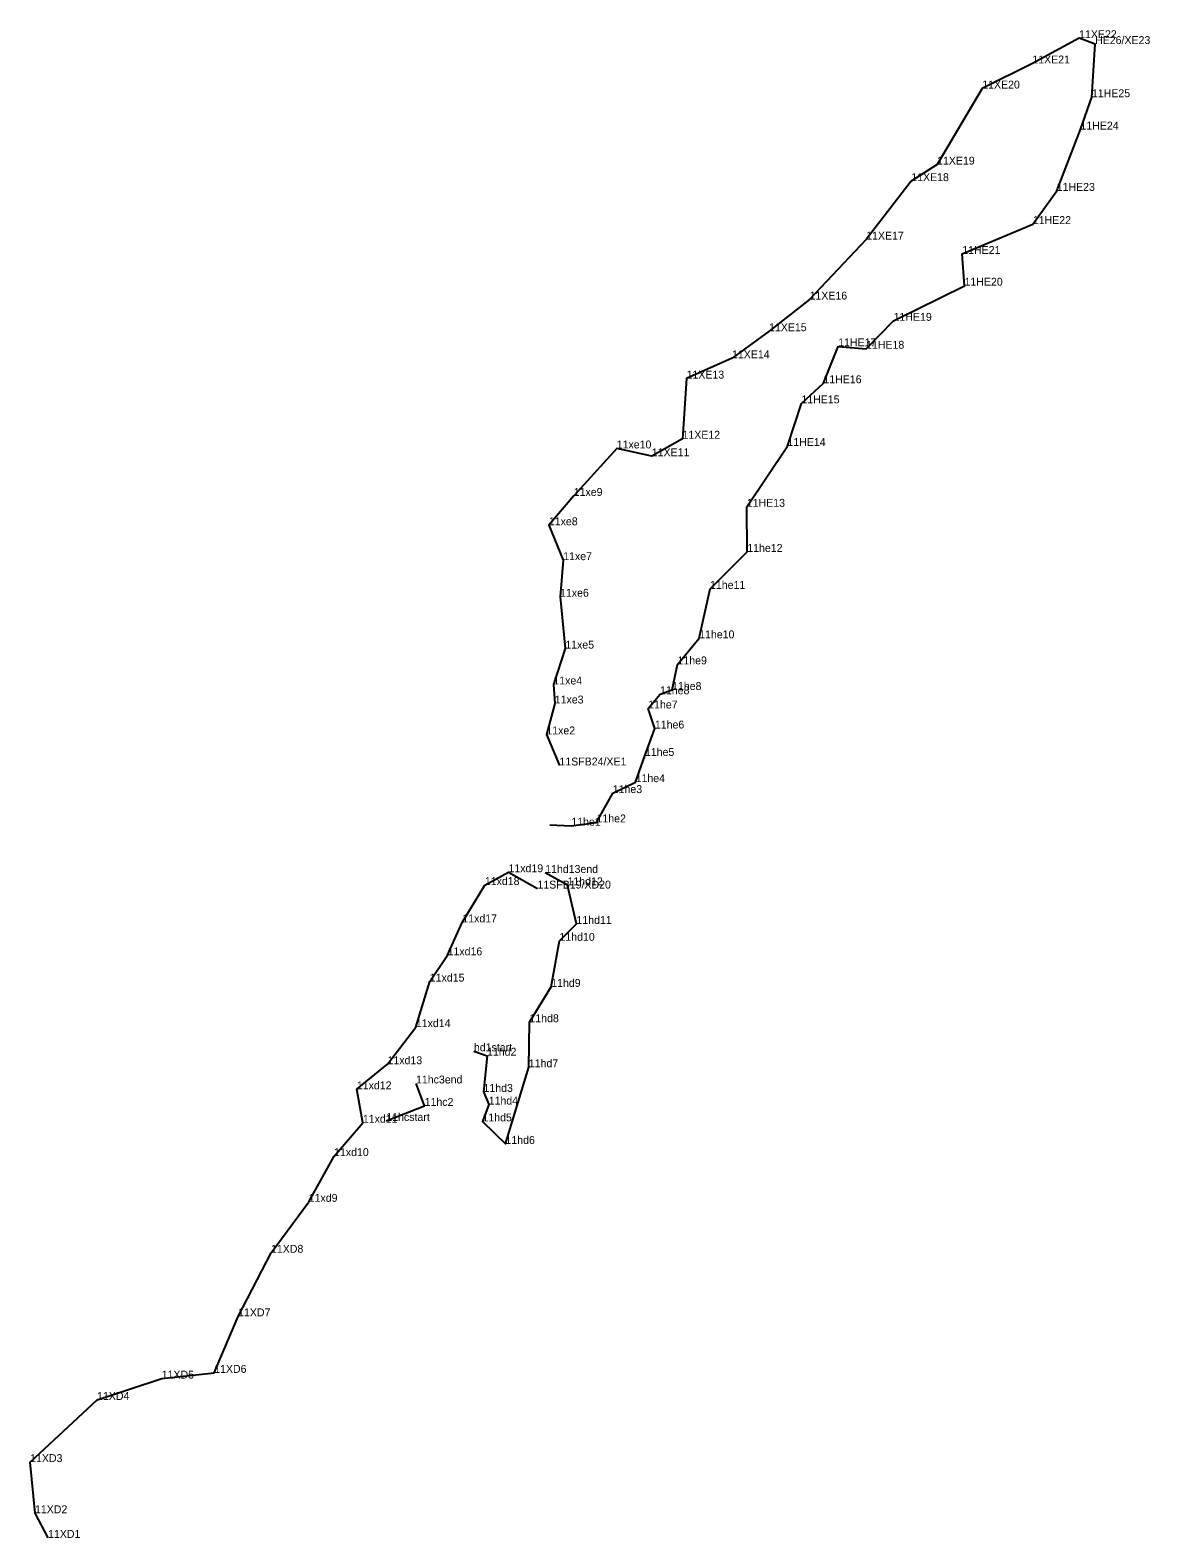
# Model space of a CAD drawing. Extents: x 2072529 to 2267990, y 436423 to 470008.
# Drawn here: x 2235708 to 2236417, y 448547 to 449501 of the extents above; entities that cross this region are included whole.
import ezdxf

# ---------------------------------------------------------------- set-up
doc = ezdxf.new("R2010")
doc.units = 0
doc.layers.add('Level 3', color=7, linetype='Continuous')
doc.layers.add('Old_Level_52', color=7, linetype='Continuous')

msp = doc.modelspace()

# ---------------------------------------------------------------- linework, layer by layer
at = {"layer": 'Level 3'}
for p, q in [((2236372.381, 449496.4), (2236372.381, 449496.4)), ((2236382.487, 449492.667), (2236382.487, 449492.667)), ((2236342.766, 449480.407), (2236342.766, 449480.407)), ((2236311.041, 449464.52), (2236311.041, 449464.52)), ((2236380.495, 449459.029), (2236380.495, 449459.029)), ((2236373.231, 449438.548), (2236373.231, 449438.548)), ((2236282.461, 449416.334), (2236282.461, 449416.334)), ((2236266.127, 449405.869), (2236266.127, 449405.869)), ((2236358.182, 449399.707), (2236358.182, 449399.707)), ((2236343.073, 449378.68), (2236343.073, 449378.68)), ((2236237.577, 449368.843), (2236237.577, 449368.843)), ((2236298.377, 449359.711), (2236298.377, 449359.711)), ((2236299.825, 449339.635), (2236299.825, 449339.635)), ((2236201.726, 449330.85), (2236201.726, 449330.85)), ((2236176.077, 449310.812), (2236176.077, 449310.812)), ((2236254.906, 449317.386), (2236254.906, 449317.386)), ((2236219.847, 449301.214), (2236219.847, 449301.214)), ((2236152.626, 449293.629), (2236152.626, 449293.629)), ((2236237.488, 449299.692), (2236237.488, 449299.692)), ((2236123.874, 449280.795), (2236123.874, 449280.795)), ((2236210.458, 449277.837), (2236210.458, 449277.837)), ((2236196.532, 449265.111), (2236196.532, 449265.111)), ((2236079.636, 449236.555), (2236079.636, 449236.555)), ((2236121.287, 449242.715), (2236121.287, 449242.715)), ((2236187.697, 449238.085), (2236187.697, 449238.085)), ((2236101.838, 449231.627), (2236101.838, 449231.627)), ((2236052.417, 449206.469), (2236052.417, 449206.469)), ((2236161.993, 449199.608), (2236161.993, 449199.608)), ((2236036.692, 449187.888), (2236036.692, 449187.888)), ((2236162.291, 449171.028), (2236162.291, 449171.028)), ((2236045.747, 449165.812), (2236045.747, 449165.812)), ((2236043.749, 449142.63), (2236043.749, 449142.63)), ((2236138.698, 449147.6), (2236138.698, 449147.6)), ((2236131.838, 449116.29), (2236131.838, 449116.29)), ((2236047.072, 449109.752), (2236047.072, 449109.752)), ((2236118.11, 449099.797), (2236118.11, 449099.797)), ((2236039.52, 449087.061), (2236039.52, 449087.061)), ((2236114.672, 449083.574), (2236114.672, 449083.574)), ((2236040.408, 449075.012), (2236040.408, 449075.012)), ((2236107.055, 449080.862), (2236107.055, 449080.862)), ((2236099.573, 449071.867), (2236099.573, 449071.867)), ((2236035.088, 449055.455), (2236035.088, 449055.455)), ((2236103.804, 449059.163), (2236103.804, 449059.163)), ((2236043.377, 449035.763), (2236043.377, 449035.763)), ((2236097.503, 449041.818), (2236097.503, 449041.818)), ((2236091.619, 449025.199), (2236091.619, 449025.199)), ((2236077.126, 449018.282), (2236077.126, 449018.282)), ((2236050.888, 448997.616), (2236050.888, 448997.616)), ((2236066.833, 448999.706), (2236066.833, 448999.706)), ((2236011.122, 448968.149), (2236011.122, 448968.149)), ((2236034.371, 448967.688), (2236034.371, 448967.688)), ((2235996.15, 448960.017), (2235996.15, 448960.017)), ((2236029.475, 448957.79), (2236029.475, 448957.79)), ((2236048.496, 448959.873), (2236048.496, 448959.873)), ((2235981.889, 448936.379), (2235981.889, 448936.379)), ((2236054.14, 448935.368), (2236054.14, 448935.368)), ((2236043.395, 448924.719), (2236043.395, 448924.719)), ((2235972.58, 448915.517), (2235972.58, 448915.517)), ((2235961.301, 448898.905), (2235961.301, 448898.905)), ((2236038.175, 448895.551), (2236038.175, 448895.551)), ((2236024.363, 448873.171), (2236024.363, 448873.171)), ((2235952.483, 448870.039), (2235952.483, 448870.039)), ((2235989.227, 448854.751), (2235989.227, 448854.751)), ((2235934.554, 448846.556), (2235934.554, 448846.556)), ((2235997.532, 448851.959), (2235997.532, 448851.959)), ((2236023.977, 448844.647), (2236023.977, 448844.647)), ((2235952.659, 448834.37), (2235952.659, 448834.37)), ((2235915.147, 448830.658), (2235915.147, 448830.658)), ((2235995.296, 448829.003), (2235995.296, 448829.003)), ((2235958.039, 448820.174), (2235958.039, 448820.174)), ((2235998.588, 448820.986), (2235998.588, 448820.986)), ((2235918.936, 448809.492), (2235918.936, 448809.492)), ((2235933.775, 448810.615), (2235933.775, 448810.615)), ((2235994.652, 448810.319), (2235994.652, 448810.319)), ((2236009.196, 448796.033), (2236009.196, 448796.033)), ((2235900.694, 448788.366), (2235900.694, 448788.366)), ((2235884.648, 448759.395), (2235884.648, 448759.395)), ((2235860.77, 448727.139), (2235860.77, 448727.139)), ((2235839.958, 448686.864), (2235839.958, 448686.864)), ((2235791.563, 448647.468), (2235791.563, 448647.468)), ((2235824.794, 448651.078), (2235824.794, 448651.078)), ((2235750.665, 448633.918), (2235750.665, 448633.918)), ((2235708.297, 448594.57), (2235708.297, 448594.57)), ((2235711.364, 448562.164), (2235711.364, 448562.164)), ((2235719.636, 448546.571), (2235719.636, 448546.571))]:
    msp.add_line(p, q, dxfattribs=at)
at = {"layer": 'Old_Level_52'}
for points in [[(2236037.3, 448998.128), (2236050.888, 448997.616), (2236066.833, 448999.706), (2236077.126, 449018.282), (2236091.619, 449025.199), (2236097.503, 449041.818), (2236103.804, 449059.163), (2236099.573, 449071.867), (2236107.055, 449080.862), (2236114.672, 449083.574), (2236118.11, 449099.797), (2236131.838, 449116.29), (2236138.698, 449147.6), (2236162.291, 449171.028), (2236161.993, 449199.608), (2236187.697, 449238.085), (2236196.532, 449265.111), (2236210.458, 449277.837), (2236219.847, 449301.214), (2236237.488, 449299.692), (2236254.906, 449317.386), (2236299.825, 449339.635), (2236298.377, 449359.711), (2236343.073, 449378.68), (2236358.182, 449399.707), (2236373.231, 449438.548), (2236380.495, 449459.029), (2236382.487, 449492.667), (2236372.381, 449496.4), (2236342.766, 449480.407), (2236311.041, 449464.52), (2236282.461, 449416.334), (2236266.127, 449405.869), (2236237.577, 449368.843), (2236201.726, 449330.85), (2236176.077, 449310.812), (2236152.626, 449293.629), (2236123.874, 449280.795), (2236121.287, 449242.715), (2236101.838, 449231.627), (2236079.636, 449236.555), (2236052.417, 449206.469), (2236036.692, 449187.888), (2236045.747, 449165.812), (2236043.749, 449142.63), (2236047.072, 449109.752), (2236039.52, 449087.061), (2236040.408, 449075.012), (2236035.088, 449055.455), (2236043.377, 449035.763)], [(2235719.636, 448546.571), (2235711.364, 448562.164), (2235708.297, 448594.57), (2235750.665, 448633.918), (2235791.563, 448647.468), (2235824.794, 448651.078), (2235839.958, 448686.864), (2235860.77, 448727.139), (2235884.648, 448759.395), (2235900.694, 448788.366), (2235918.936, 448809.492), (2235915.147, 448830.658), (2235934.554, 448846.556), (2235952.483, 448870.039), (2235961.301, 448898.905), (2235972.58, 448915.517), (2235981.889, 448936.379), (2235996.15, 448960.017), (2236011.122, 448968.149), (2236029.475, 448957.79)], [(2235989.227, 448854.751), (2235997.532, 448851.959), (2235995.296, 448829.003), (2235998.588, 448820.986), (2235994.652, 448810.319), (2236009.196, 448796.033), (2236023.977, 448844.647), (2236024.363, 448873.171), (2236038.175, 448895.551), (2236043.395, 448924.719), (2236054.14, 448935.368), (2236048.496, 448959.873), (2236034.371, 448967.688)], [(2235933.775, 448810.615), (2235958.039, 448820.174), (2235952.659, 448834.37)]]:
    msp.add_lwpolyline(points, dxfattribs=at)

# ---------------------------------------------------------------- texts
for s, p in [('11XE22', (2236372.381, 449496.4)), ('HE26/XE23', (2236382.487, 449492.667)), ('11XE21', (2236342.766, 449480.407)), ('11XE20', (2236311.041, 449464.52)), ('11HE25', (2236380.495, 449459.029)), ('11HE24', (2236373.231, 449438.548)), ('11XE19', (2236282.461, 449416.334)), ('11XE18', (2236266.127, 449405.869)), ('11HE23', (2236358.182, 449399.707)), ('11HE22', (2236343.073, 449378.68)), ('11XE17', (2236237.577, 449368.843)), ('11HE21', (2236298.377, 449359.711)), ('11HE20', (2236299.825, 449339.635)), ('11XE16', (2236201.726, 449330.85)), ('11HE19', (2236254.906, 449317.386)), ('11XE15', (2236176.077, 449310.812)), ('11HE17', (2236219.847, 449301.214)), ('11HE18', (2236237.488, 449299.692)), ('11XE14', (2236152.626, 449293.629)), ('11XE13', (2236123.874, 449280.795)), ('11HE16', (2236210.458, 449277.837)), ('11HE15', (2236196.532, 449265.111)), ('11XE12', (2236121.287, 449242.715)), ('11xe10', (2236079.636, 449236.555)), ('11XE11', (2236101.838, 449231.627)), ('11HE14', (2236187.697, 449238.085)), ('11xe9', (2236052.417, 449206.469)), ('11HE13', (2236161.993, 449199.608)), ('11xe8', (2236036.692, 449187.888)), ('11xe7', (2236045.747, 449165.812)), ('11he12', (2236162.291, 449171.028)), ('11he11', (2236138.698, 449147.6)), ('11xe6', (2236043.749, 449142.63)), ('11he10', (2236131.838, 449116.29)), ('11xe5', (2236047.072, 449109.752)), ('11he9', (2236118.11, 449099.797)), ('11xe4', (2236039.52, 449087.061)), ('11he8', (2236107.055, 449080.862)), ('11he8', (2236114.672, 449083.574)), ('11xe3', (2236040.408, 449075.012)), ('11he7', (2236099.573, 449071.867)), ('11he6', (2236103.804, 449059.163)), ('11xe2', (2236035.088, 449055.455)), ('11he5', (2236097.503, 449041.818)), ('11SFB24/XE1', (2236043.377, 449035.763)), ('11he4', (2236091.619, 449025.199)), ('11he3', (2236077.126, 449018.282)), ('11he1', (2236050.888, 448997.616)), ('11he2', (2236066.833, 448999.706)), ('11xd19', (2236011.122, 448968.149)), ('11hd13end', (2236034.371, 448967.688)), ('11xd18', (2235996.15, 448960.017)), ('11SFB19/XD20', (2236029.475, 448957.79)), ('11hd12', (2236048.496, 448959.873)), ('11xd17', (2235981.889, 448936.379)), ('11hd11', (2236054.14, 448935.368)), ('11hd10', (2236043.395, 448924.719)), ('11xd16', (2235972.58, 448915.517)), ('11xd15', (2235961.301, 448898.905)), ('11hd9', (2236038.175, 448895.551)), ('11xd14', (2235952.483, 448870.039)), ('11hd8', (2236024.363, 448873.171)), ('hd1start', (2235989.227, 448854.751)), ('11hd2', (2235997.532, 448851.959)), ('11xd13', (2235934.554, 448846.556)), ('11hd7', (2236023.977, 448844.647)), ('11xd12', (2235915.147, 448830.658)), ('11hc3end', (2235952.581, 448834.347)), ('11hd3', (2235995.296, 448829.003)), ('11hc2', (2235958.039, 448820.174)), ('11hd4', (2235998.588, 448820.986)), ('11xd11', (2235918.936, 448809.492)), ('11hcstart', (2235933.775, 448810.615)), ('11hd5', (2235994.652, 448810.319)), ('11hd6', (2236009.196, 448796.033)), ('11xd10', (2235900.694, 448788.366)), ('11xd9', (2235884.648, 448759.395)), ('11XD8', (2235860.77, 448727.139)), ('11XD7', (2235839.958, 448686.864)), ('11XD5', (2235791.563, 448647.468)), ('11XD6', (2235824.794, 448651.078)), ('11XD4', (2235750.665, 448633.918)), ('11XD3', (2235708.297, 448594.57)), ('11XD2', (2235711.364, 448562.164)), ('11XD1', (2235719.636, 448546.571))]:
    msp.add_text(s, height=5).set_placement(p)

doc.saveas('drawing.dxf')
